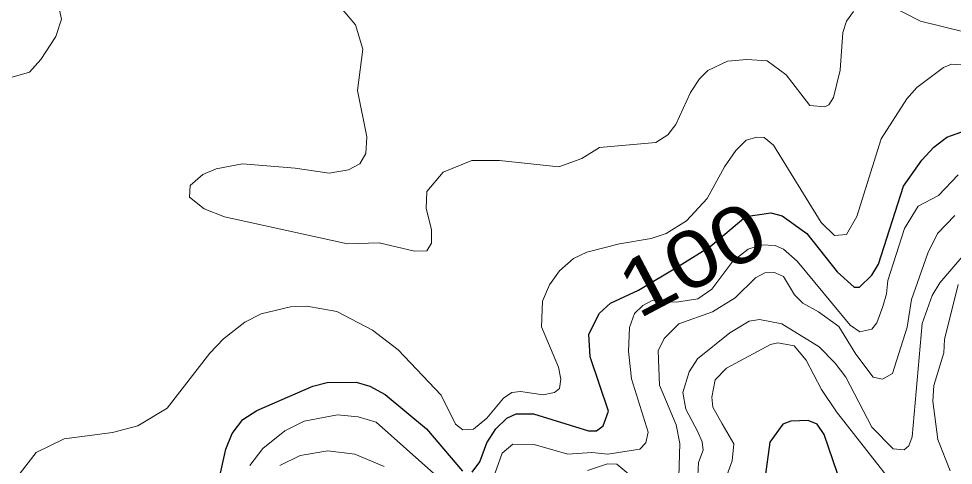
# Model space of a CAD drawing. Extents: x 673.6 to 698.9, y 7012 to 7040.1.
# Drawn here: x 685.993 to 687.311, y 7019.586 to 7020.215 of the extents above; entities that cross this region are included whole.
import ezdxf
from ezdxf.enums import TextEntityAlignment as Align

# ---------------------------------------------------------------- set-up
doc = ezdxf.new("R2010")
doc.units = 0
doc.header["$LTSCALE"] = 0.032
doc.layers.add('1', color=7, linetype='Continuous', lineweight=25)
doc.layers.add('2', color=7, linetype='Continuous', lineweight=13)
doc.layers.add('61', color=7, linetype='Continuous')

msp = doc.modelspace()

# ---------------------------------------------------------------- linework, layer by layer
at = {"layer": '1'}
for points in [[(686.6322, 7019.5759), (686.6433, 7019.5906), (686.653, 7019.6172), (686.6655, 7019.6373), (686.6811, 7019.6521), (686.6943, 7019.6584), (686.719, 7019.6581), (686.7966, 7019.6341), (686.8079, 7019.6343), (686.8173, 7019.6415), (686.8248, 7019.6621), (686.7988, 7019.7384), (686.797, 7019.7704), (686.8118, 7019.8), (686.8274, 7019.814), (686.867, 7019.8323), (686.9241, 7019.8667), (686.9678, 7019.8939), (687.0181, 7019.9363), (687.0534, 7019.9415), (687.0697, 7019.9372), (687.1045, 7019.9124), (687.1473, 7019.8582), (687.1709, 7019.8368), (687.1785, 7019.8365), (687.1958, 7019.8537), (687.2053, 7019.8693), (687.2407, 7019.9792), (687.2664, 7020.0156), (687.2835, 7020.0342), (687.302, 7020.048), (687.3348, 7020.0598)], [(686.2773, 7019.5744), (686.285, 7019.6084), (686.2939, 7019.6305), (686.3089, 7019.6504), (686.3286, 7019.6628), (686.4078, 7019.6974), (686.428, 7019.7024), (686.4686, 7019.703), (686.4879, 7019.6973), (686.5096, 7019.6856), (686.5678, 7019.6372), (686.6188, 7019.5772)], [(687.1474, 7019.5742), (687.1288, 7019.6293), (687.1191, 7019.6435), (687.1063, 7019.6488), (687.0818, 7019.648), (687.0703, 7019.6436), (687.0522, 7019.6185), (687.032, 7019.4701)]]:
    msp.add_lwpolyline(points, dxfattribs=at)
at = {"layer": '2'}
for points in [[(685.9837, 7020.1327), (686.0079, 7020.1397), (686.0241, 7020.1574), (686.0452, 7020.19), (686.0532, 7020.2142), (686.0504, 7020.2269), (686.0237, 7020.2518), (685.9683, 7020.2661)], [(687.075, 7020.1358), (687.0482, 7020.1555), (687.0197, 7020.1575), (686.9925, 7020.155), (686.9649, 7020.1421), (686.9529, 7020.1305), (686.9401, 7020.1111), (686.9198, 7020.0657), (686.9085, 7020.0513), (686.8915, 7020.0406), (686.8117, 7020.0336), (686.7871, 7020.0179), (686.7545, 7020.0064), (686.6711, 7020.0153), (686.6318, 7020.0154), (686.5916, 7019.9989), (686.5686, 7019.9715), (686.5677, 7019.9477), (686.575, 7019.9181), (686.5751, 7019.8988), (686.5682, 7019.888), (686.5509, 7019.8874), (686.5012, 7019.8994), (686.4564, 7019.8979), (686.2831, 7019.936), (686.2543, 7019.947), (686.2338, 7019.9636), (686.2345, 7019.9802), (686.2524, 7019.9953), (686.2715, 7020.0034), (686.3085, 7020.0103), (686.3828, 7020.0046), (686.4307, 7019.9974), (686.4577, 7020.002), (686.474, 7020.0105), (686.4824, 7020.0252), (686.4838, 7020.0485), (686.4708, 7020.1137), (686.4781, 7020.1722), (686.4677, 7020.2065), (686.4496, 7020.2279)], [(687.4265, 7020.2287), (687.4245, 7020.184), (687.42, 7020.1751), (687.4103, 7020.1674), (687.3943, 7020.1688), (687.365, 7020.1833), (687.3294, 7020.1957), (687.2644, 7020.2115), (687.2187, 7020.2349)], [(687.1703, 7020.2251), (687.1602, 7020.2114), (687.1553, 7020.1957), (687.1512, 7020.1426)], [(687.3235, 7020.1499), (687.3083, 7020.1509), (687.297, 7020.1461), (687.2594, 7020.1179), (687.2453, 7020.1022), (687.2091, 7020.0459), (687.1748, 7019.9362), (687.1602, 7019.9109), (687.1435, 7019.9093), (687.1245, 7019.9276), (687.0571, 7020.037), (687.0442, 7020.0474), (687.0337, 7020.0481), (687.0189, 7020.044), (687.0044, 7020.0295), (686.9881, 7020.0062), (686.9638, 7019.9617), (686.9348, 7019.93), (686.9061, 7019.9123), (686.8847, 7019.9055), (686.8401, 7019.8979), (686.7942, 7019.8859), (686.7754, 7019.8771), (686.7553, 7019.8595), (686.7412, 7019.8399), (686.7315, 7019.8172), (686.7303, 7019.7806), (686.7543, 7019.7241)], [(687.1512, 7020.1426), (687.1419, 7020.1039), (687.1353, 7020.0935), (687.1299, 7020.0906), (687.1087, 7020.0926), (687.075, 7020.1358)], [(687.3179, 7019.9949), (687.2899, 7019.9661), (687.2612, 7019.951), (687.2421, 7019.9194), (687.2186, 7019.8461), (687.2167, 7019.8273), (687.2114, 7019.8095), (687.2032, 7019.7864), (687.1958, 7019.7775), (687.1791, 7019.7738), (687.1656, 7019.7832), (687.0909, 7019.8735), (687.0714, 7019.8902), (687.0599, 7019.8954), (687.0402, 7019.8962), (687.0215, 7019.8901), (686.9999, 7019.8732), (686.9705, 7019.8341), (686.9507, 7019.8204), (686.9206, 7019.8154), (686.9046, 7019.8162), (686.886, 7019.8177), (686.8728, 7019.8108), (686.8615, 7019.7998), (686.854, 7019.7797), (686.8528, 7019.7467), (686.857, 7019.7077), (686.8807, 7019.6325), (686.8771, 7019.6174), (686.8688, 7019.6085), (686.8236, 7019.6013), (686.801, 7019.6037), (686.7674, 7019.6013), (686.7197, 7019.6151), (686.6898, 7019.6154), (686.6746, 7019.6026), (686.6508, 7019.5357)], [(686.9235, 7019.5533), (686.9251, 7019.6164), (686.9201, 7019.6426), (686.8964, 7019.6985), (686.8948, 7019.7471), (686.9029, 7019.7644), (686.9236, 7019.7852), (686.9711, 7019.8018), (687.0032, 7019.8217), (687.0317, 7019.85), (687.0452, 7019.8567), (687.0588, 7019.8576), (687.0712, 7019.8517), (687.087, 7019.826), (687.0985, 7019.8141), (687.1206, 7019.8021), (687.1496, 7019.7812), (687.1735, 7019.7425), (687.198, 7019.7097), (687.2112, 7019.7073), (687.2251, 7019.7149), (687.2456, 7019.7804), (687.2521, 7019.8195), (687.2749, 7019.8848), (687.2886, 7019.9121), (687.3129, 7019.9378)], [(687.3514, 7019.9124), (687.2917, 7019.8427), (687.2813, 7019.8252), (687.2671, 7019.7853), (687.253, 7019.6258), (687.2483, 7019.613), (687.2417, 7019.6075), (687.2259, 7019.6087), (687.1962, 7019.6393), (687.1593, 7019.7097), (687.1443, 7019.7297), (687.1215, 7019.7524), (687.0689, 7019.7852), (687.0375, 7019.7911), (687.023, 7019.789), (686.9957, 7019.7723), (686.9503, 7019.7355), (686.9382, 7019.7176), (686.9293, 7019.6883), (686.9335, 7019.665), (686.9508, 7019.633), (686.9568, 7019.6189), (686.9583, 7019.607), (686.9516, 7019.5898), (686.9499, 7019.5614)], [(687.3064, 7019.5779), (687.2889, 7019.6221), (687.2818, 7019.6761), (687.2835, 7019.6981), (687.2974, 7019.7442), (687.2983, 7019.7632), (687.3179, 7019.8406)], [(686.7004, 7019.6899), (686.6885, 7019.6883), (686.6765, 7019.6804), (686.6529, 7019.6519), (686.6341, 7019.6366), (686.6194, 7019.6358), (686.609, 7019.6438), (686.5884, 7019.6847), (686.528, 7019.7485), (686.4916, 7019.7762), (686.4416, 7019.8026), (686.3992, 7019.8099), (686.3759, 7019.8091), (686.3348, 7019.7991), (686.3115, 7019.7873), (686.2815, 7019.7637), (686.2626, 7019.7439), (686.2021, 7019.6663), (686.1606, 7019.6415), (686.1249, 7019.632), (686.057, 7019.6232), (686.0173, 7019.6037), (685.9948, 7019.5746), (685.9688, 7019.5193)], [(686.988, 7019.5623), (686.9992, 7019.5921), (687.0015, 7019.6159), (686.9851, 7019.6442), (686.9717, 7019.6674), (686.9703, 7019.6815), (686.9752, 7019.7061), (686.991, 7019.7228), (687.0533, 7019.7557), (687.0636, 7019.7581), (687.0864, 7019.7539), (687.1036, 7019.734), (687.125, 7019.6923), (687.1462, 7019.6609), (687.2181, 7019.5695)], [(686.7543, 7019.7241), (686.7574, 7019.7069), (686.7557, 7019.6941), (686.7483, 7019.6881), (686.7325, 7019.6851), (686.7004, 7019.6899)], [(686.5781, 7019.5743), (686.497, 7019.6463), (686.4718, 7019.6538), (686.4426, 7019.657), (686.3956, 7019.6479), (686.3683, 7019.6342), (686.3373, 7019.6092), (686.319, 7019.5854)], [(686.3612, 7019.5854), (686.3897, 7019.5996), (686.4288, 7019.6061), (686.4669, 7019.6016), (686.5084, 7019.5842)], [(686.795, 7019.5782), (686.8232, 7019.588), (686.8362, 7019.5873), (686.8587, 7019.5683)]]:
    msp.add_lwpolyline(points, dxfattribs=at)

# ---------------------------------------------------------------- texts
at = {"layer": '61', "width": 1.2}
msp.add_text('100', height=0.08, rotation=27.819, dxfattribs=at).set_placement((686.9614, 7019.8411), align=Align.CENTER)

doc.saveas('drawing.dxf')
